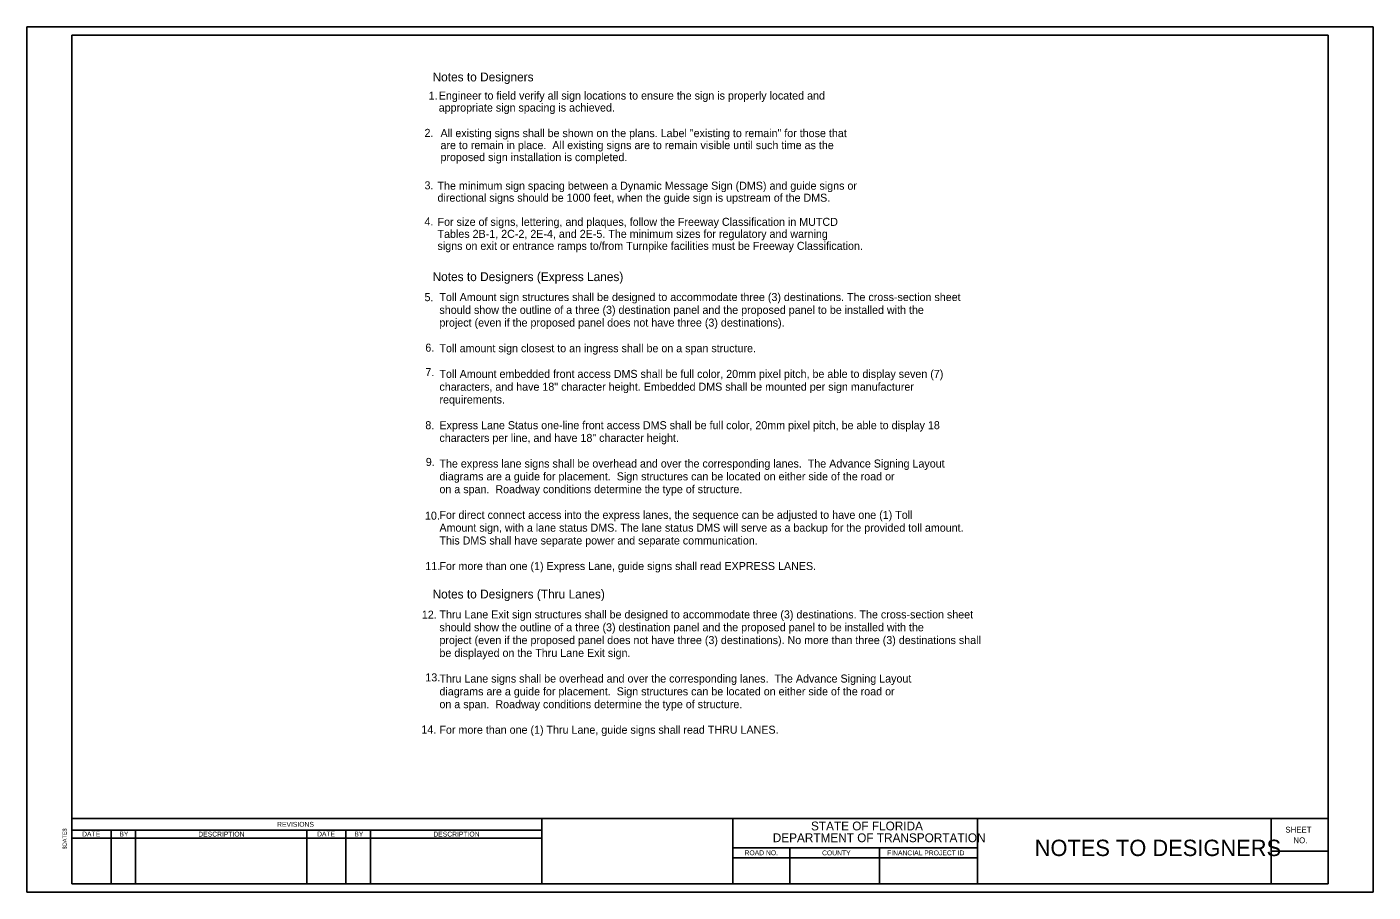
# Model space of a CAD drawing. Extents: x 17890229 to 17891384, y 17891845 to 17892587.
import ezdxf

# ---------------------------------------------------------------- set-up
doc = ezdxf.new("R2010")
doc.units = 0
for name, color, linetype in [('PlotBorder_dp', 7, 'Continuous'), ('SheetBorder_dp', 7, 'Continuous'), ('SheetLines_dp', 7, 'Continuous'), ('TextLabel', 7, 'Continuous'), ('TextMinor', 7, 'Continuous'), ('TextMisc', 7, 'Continuous')]:
    doc.layers.add(name, color=color, linetype=linetype)

msp = doc.modelspace()

# ---------------------------------------------------------------- linework, layer by layer
at = {"layer": 'PlotBorder_dp'}
msp.add_lwpolyline([(17890228.6, 17891844.7), (17891383.6, 17891844.7), (17891383.6, 17892586.7), (17890228.6, 17892586.7)], close=True, dxfattribs=at)
at = {"layer": 'SheetBorder_dp'}
for p, q in [((17890267.1, 17892579.7), (17890267.1, 17891851.7)), ((17890267.1, 17892579.7), (17891345.1, 17892579.7)), ((17891345.1, 17892579.7), (17891345.1, 17891851.7)), ((17890267.1, 17891907.7), (17891345.1, 17891907.7)), ((17890267.1, 17891851.7), (17891345.1, 17891851.7))]:
    msp.add_line(p, q, dxfattribs=at)
at = {"layer": 'SheetLines_dp'}
for p, q in [((17890267.1, 17891897.9), (17890670.3, 17891897.9)), ((17890300.7, 17891897.9), (17890300.7, 17891851.7)), ((17890321.7, 17891897.9), (17890321.7, 17891851.7)), ((17890468.7, 17891897.9), (17890468.7, 17891851.7)), ((17890502.3, 17891897.9), (17890502.3, 17891851.7)), ((17890523.3, 17891897.9), (17890523.3, 17891851.7)), ((17890670.3, 17891907.7), (17890670.3, 17891851.7)), ((17890834.1, 17891907.7), (17890834.1, 17891851.7)), ((17891044.1, 17891851.7), (17891044.1, 17891907.7)), ((17891296.1, 17891851.7), (17891296.1, 17891907.7)), ((17890267.1, 17891890.9), (17890670.3, 17891890.9)), ((17890834.1, 17891882.5), (17891044.1, 17891882.5)), ((17890834.1, 17891874.1), (17891044.1, 17891874.1)), ((17890883.1, 17891882.5), (17890883.1, 17891851.7)), ((17890960.1, 17891882.5), (17890960.1, 17891851.7)), ((17891296.1, 17891879.7), (17891345.1, 17891879.7))]:
    msp.add_line(p, q, dxfattribs=at)

# ---------------------------------------------------------------- texts
at = {"layer": 'TextLabel'}
for s, height, p in [('Notes to Designers', 7.62, (17890576.6, 17892540)), ('1.', 6.87, (17890573.2, 17892524.3)), ('  appropriate sign spacing is achieved.', 6.868, (17890576.8, 17892514.1)), ('  Engineer to field verify all sign locations to ensure the sign is properly located and', 6.868, (17890576.8, 17892524.4)), ('2.', 6.87, (17890569.7, 17892492.4)), ('  All existing signs shall be shown on the plans. Label "existing to remain" for those that ', 6.868, (17890578.3, 17892492.2)), ('  are to remain in place.  All existing signs are to remain visible until such time as the', 6.868, (17890578.3, 17892481.9)), ('  proposed sign installation is completed.', 6.868, (17890578.3, 17892471.6)), ('3.', 6.87, (17890569.7, 17892447.4)), (' The minimum sign spacing between a Dynamic Message Sign (DMS) and guide signs or', 6.868, (17890578.3, 17892447.1)), (' directional signs should be 1000 feet, when the guide sign is upstream of the DMS.', 6.868, (17890578.3, 17892436.8)), ('4.', 6.87, (17890569.7, 17892416.4)), (' For size of signs, lettering, and plaques, follow the Freeway Classification in MUTCD', 6.868, (17890578.3, 17892416.1)), (' Tables 2B-1, 2C-2, 2E-4, and 2E-5. The minimum sizes for regulatory and warning', 6.868, (17890578.3, 17892405.8)), (' signs on exit or entrance ramps to/from Turnpike facilities must be Freeway Classification.', 6.868, (17890578.3, 17892395.5)), ('Notes to Designers (Express Lanes)', 7.62, (17890576.6, 17892368.7)), ('5.', 6.87, (17890569.7, 17892351.5)), ('  Toll Amount sign structures shall be designed to accommodate three (3) destinations. The cross-section sheet', 6.8678, (17890577.4, 17892351.6)), ('  should show the outline of a three (3) destination panel and the proposed panel to be installed with the', 6.8678, (17890577.4, 17892340.6)), ('  project (even if the proposed panel does not have three (3) destinations).  ', 6.868, (17890577.4, 17892329.7)), ('6.', 6.87, (17890570.4, 17892308.2)), ('  Toll amount sign closest to an ingress shall be on a span structure.', 6.868, (17890577.4, 17892307.7)), ('7.', 6.87, (17890570.4, 17892287.2)), ('  Toll Amount embedded front access DMS shall be full color, 20mm pixel pitch, be able to display seven (7)', 6.8678, (17890577.4, 17892285.7)), ('  characters, and have 18" character height. Embedded DMS shall be mounted per sign manufacturer', 6.868, (17890577.4, 17892274.7)), ('  requirements.', 6.868, (17890577.4, 17892263.7)), ('8.', 6.87, (17890570.4, 17892241.7)), ('  Express Lane Status one-line front access DMS shall be full color, 20mm pixel pitch, be able to display 18', 6.8678, (17890577.4, 17892241.7)), ('  characters per line, and have 18" character height.', 6.868, (17890577.4, 17892230.8)), ('9.', 6.87, (17890570.8, 17892210.2)), ('  The express lane signs shall be overhead and over the corresponding lanes.  The Advance Signing Layout', 6.8678, (17890577.4, 17892208.8)), ('  diagrams are a guide for placement.  Sign structures can be located on either side of the road or', 6.868, (17890577.4, 17892197.8)), ('  on a span.  Roadway conditions determine the type of structure.', 6.868, (17890577.4, 17892186.8)), ('10.', 6.87, (17890570.1, 17892164.1)), ('  For direct connect access into the express lanes, the sequence can be adjusted to have one (1) Toll', 6.8678, (17890577.4, 17892164.8)), ('  Amount sign, with a lane status DMS. The lane status DMS will serve as a backup for the provided toll amount.', 6.8678, (17890577.4, 17892153.8)), ('  This DMS shall have separate power and separate communication.', 6.868, (17890577.4, 17892142.8)), ('  For more than one (1) Express Lane, guide signs shall read EXPRESS LANES.', 6.868, (17890577.4, 17892120.9)), ('11.', 6.87, (17890570.4, 17892120.9)), ('Notes to Designers (Thru Lanes)', 7.62, (17890576.6, 17892096.5)), ('12.', 6.87, (17890567.4, 17892079.2)), ('  Thru Lane Exit sign structures shall be designed to accommodate three (3) destinations. The cross-section sheet', 6.8678, (17890577.4, 17892079.4)), ('  should show the outline of a three (3) destination panel and the proposed panel to be installed with the', 6.8678, (17890577.4, 17892068.4)), ('  project (even if the proposed panel does not have three (3) destinations). No more than three (3) destinations shall', 6.8678, (17890577.4, 17892057.4)), ('  be displayed on the Thru Lane Exit sign.', 6.868, (17890577.4, 17892046.4)), ('13.', 6.87, (17890570.4, 17892025.4)), ('  Thru Lane signs shall be overhead and over the corresponding lanes.  The Advance Signing Layout', 6.868, (17890577.4, 17892024.4)), ('  diagrams are a guide for placement.  Sign structures can be located on either side of the road or', 6.868, (17890577.4, 17892013.4)), ('  on a span.  Roadway conditions determine the type of structure.', 6.868, (17890577.4, 17892002.4)), ('14.', 6.87, (17890567, 17891980.7)), ('  For more than one (1) Thru Lane, guide signs shall read THRU LANES.', 6.868, (17890577.4, 17891980.5))]:
    msp.add_text(s, height=height, dxfattribs=at).set_placement(p)
at = {"layer": 'TextMinor'}
msp.add_text('$DATE$', height=3.43, rotation=90, dxfattribs=at).set_placement((17890262.6, 17891881.4))
at = {"layer": 'TextMisc'}
for s, height, p in [('REVISIONS', 4.2, (17890443.2, 17891900.7)), ('STATE OF FLORIDA', 7.56, (17890901.3, 17891897.6)), ('BY', 4.2, (17890307.9, 17891892.4)), ('BY', 4.2, (17890509.5, 17891892.4)), ('DEPARTMENT OF TRANSPORTATION', 7.56, (17890868.5, 17891887.5)), ('NOTES TO DESIGNERS', 14.017, (17891093.2, 17891875.6)), ('ROAD NO.', 4.2, (17890844.3, 17891876.3)), ('COUNTY', 4.2, (17890910.8, 17891876.2)), ('FINANCIAL PROJECT ID', 4.2, (17890966.6, 17891876.2))]:
    msp.add_text(s, height=height, dxfattribs=at).set_placement(p)
for s, height, rotation, p in [('SHEET', 5.04, 359.8607, (17891308.3, 17891895.7)), ('DATE', 4.2, 359.8693, (17890275.9, 17891892.4)), ('DESCRIPTION', 4.199, 0.0498, (17890375.6, 17891892.3)), ('DATE', 4.2, 359.8693, (17890477.5, 17891892.4)), ('DESCRIPTION', 4.199, 0.0498, (17890577.3, 17891892.3)), ('NO.', 5.04, 359.8607, (17891315.2, 17891886.6))]:
    msp.add_text(s, height=height, rotation=rotation, dxfattribs=at).set_placement(p)

doc.saveas('drawing.dxf')
